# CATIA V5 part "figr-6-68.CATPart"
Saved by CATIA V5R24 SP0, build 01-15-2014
Part number: Part2
Bounding box of the stored display mesh (mm): x -48.023 to 47.984, y -42.839 to 53.196, z 0 to 122.21
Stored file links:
  D:\KAVITA\CATIA V5-6R2014 Project_ Kavita\CATIA V5-6R2014_partfiles\Partfiles\c06_catia_v5-6r2014_prt\figr-6-68.CATPart
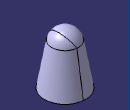
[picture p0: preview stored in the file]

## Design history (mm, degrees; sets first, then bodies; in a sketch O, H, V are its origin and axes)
Body1 (main body)
  Sketch1 on yz-plane, origin (0, 0, 0), H (0, 1, 0), V (0, 0, 1)
    axis line L1 (-55.8323, 90.9269) -> (61.0167, 90.9269)
    arc A1 centre (5.1844, 90.9269) radius 31.5054 from (36.6898, 90.9269) to (-26.3209, 90.9269) ccw
    point P3 (5.1844, 90.9269)
    point P4 (36.6898, 90.9269)
    point P5 (-26.3209, 90.9269)
    line L2 (-26.3209, 90.9269) -> (36.6898, 90.9269)
    horizontal: L1 H, L2 H
    coincidence: P3 L1, P4 L1, P5 L1
  Shaft1: profile Sketch1, axis Sketch1.L1, angle 360
  Draft1: Angle 10, Parting xy-plane, PullDir (0, 0, 1), SupportToDraft face of Shaft1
